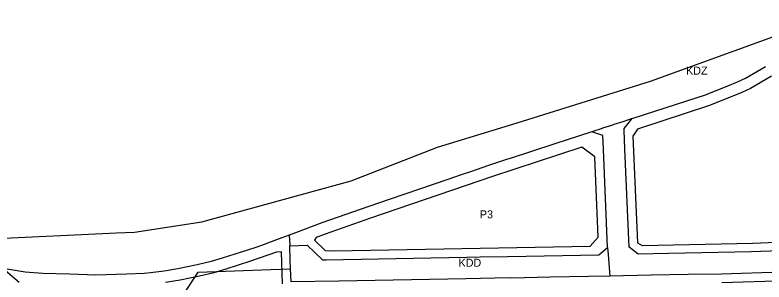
# Model space of a CAD drawing. Extents: x 7428080 to 7432143, y 5545880 to 5549217.
# Drawn here: x 7428821 to 7429340, y 5547123 to 5547308 of the extents above; entities that cross this region are included whole.
import ezdxf

# ---------------------------------------------------------------- set-up
doc = ezdxf.new("R2010")
doc.units = 0
for name, color, linetype in [('CZ_L_linie rozgraniczające tereny o różnym przeznaczeniu oraz różnych warunkach ich zabudowy i zagospodarowania', 7, 'Continuous'), ('CZ_L_maksymalne nieprzekraczalne linie zabudowy', 7, 'Continuous'), ('CZ_L_opisy_linie rozgraniczające tereny o różnym przeznaczeniu oraz różnych warunkach ich zabudowy i zagospodarowania', 7, 'Continuous'), ('info', 7, 'Continuous')]:
    doc.layers.add(name, color=color, linetype=linetype)

msp = doc.modelspace()

# ---------------------------------------------------------------- linework, layer by layer
at = {"layer": 'CZ_L_linie rozgraniczające tereny o różnym przeznaczeniu oraz różnych warunkach ich zabudowy i zagospodarowania'}
for p, q in [((7429327.56, 5547264.7), (7429341.29, 5547272.65)), ((7429321.92, 5547262.06), (7429327.56, 5547264.7)), ((7429299.72, 5547253.05), (7429315.35, 5547259.36)), ((7429315.35, 5547259.36), (7429321.92, 5547262.06)), ((7429272.6, 5547244.17), (7429299.72, 5547253.05)), ((7429248.99, 5547236.51), (7429272.6, 5547244.17)), ((7429235.22, 5547232.03), (7429228.35, 5547229.8)), ((7429236.15, 5547232.33), (7429235.22, 5547232.03)), ((7429242.37, 5547234.36), (7429236.15, 5547232.33)), ((7429243.13, 5547234.6), (7429242.37, 5547234.36)), ((7429243.25, 5547234.64), (7429243.13, 5547234.6)), ((7429248.99, 5547236.51), (7429243.25, 5547234.64)), ((7429243.34, 5547229.61), (7429248.99, 5547236.51)), ((7429220.98, 5547227.4), (7429194.56, 5547218.81)), ((7429228.18, 5547229.74), (7429220.98, 5547227.4)), ((7429228.55, 5547224.8), (7429220.98, 5547227.4)), ((7429228.35, 5547229.8), (7429228.18, 5547229.74)), ((7429243.38, 5547228.52), (7429243.34, 5547229.61)), ((7429243.93, 5547215.27), (7429243.38, 5547228.52)), ((7429228.95, 5547215.29), (7429228.55, 5547224.8)), ((7429194.56, 5547218.81), (7429164.27, 5547208.88)), ((7429231.75, 5547147.15), (7429228.95, 5547215.29)), ((7429246.74, 5547147.43), (7429243.93, 5547215.27)), ((7429158.43, 5547206.95), (7429148.58, 5547203.66)), ((7429161.8, 5547208.07), (7429158.43, 5547206.95)), ((7429164.27, 5547208.88), (7429161.8, 5547208.07)), ((7429148.58, 5547203.66), (7429137.61, 5547199.91)), ((7429130.34, 5547197.42), (7429121.21, 5547194.29)), ((7429137.61, 5547199.91), (7429130.34, 5547197.42)), ((7429121.21, 5547194.29), (7429081.1, 5547180.55)), ((7429081.1, 5547180.55), (7429066.41, 5547175.5)), ((7429066.41, 5547175.5), (7429033.84, 5547164.13)), ((7429033.84, 5547164.13), (7429015.51, 5547157.29)), ((7429011.21, 5547155.68), (7429005.98, 5547153.73)), ((7429015.51, 5547157.29), (7429011.21, 5547155.68)), ((7429011.21, 5547155.68), (7429011.46, 5547148.89)), ((7428998.58, 5547150.97), (7428991.91, 5547148.54)), ((7429005.98, 5547153.73), (7428998.58, 5547150.97)), ((7429011.46, 5547148.89), (7429011.49, 5547148.19)), ((7429011.49, 5547148.19), (7429023.48, 5547148.64)), ((7429023.48, 5547148.64), (7429034.29, 5547138.6)), ((7428982.2, 5547145.26), (7428964.74, 5547139.68)), ((7428987.98, 5547147.1), (7428982.2, 5547145.26)), ((7428991.91, 5547148.54), (7428987.98, 5547147.1)), ((7429011.86, 5547138.2), (7429011.49, 5547148.19)), ((7429225.71, 5547142.04), (7429231.75, 5547147.15)), ((7429231.75, 5547147.15), (7429232.19, 5547142.16)), ((7429252.97, 5547142.55), (7429246.74, 5547147.43)), ((7429331.73, 5547144.02), (7429274.15, 5547142.94)), ((7429351.35, 5547144.79), (7429331.73, 5547144.02)), ((7428964.74, 5547139.68), (7428956.98, 5547137.37)), ((7429034.29, 5547138.6), (7429036.78, 5547138.65)), ((7429036.78, 5547138.65), (7429109.22, 5547139.96)), ((7429109.22, 5547139.96), (7429134.17, 5547140.41)), ((7429134.17, 5547140.41), (7429143.54, 5547140.58)), ((7429143.54, 5547140.58), (7429162.55, 5547140.92)), ((7429162.55, 5547140.92), (7429162.61, 5547140.86)), ((7429162.61, 5547140.86), (7429225.71, 5547142.04)), ((7429232.19, 5547142.16), (7429233.5, 5547127.25)), ((7429274.15, 5547142.94), (7429252.97, 5547142.55)), ((7428947.3, 5547135.11), (7428933.97, 5547132.32)), ((7428956.98, 5547137.37), (7428947.3, 5547135.11)), ((7429012.08, 5547132.28), (7429011.86, 5547138.2)), ((7428812.73, 5547132.54), (7428823.86, 5547123.08)), ((7428827.96, 5547129.92), (7428814.29, 5547132.24)), ((7428840.36, 5547129.06), (7428827.96, 5547129.92)), ((7428858.99, 5547128.56), (7428840.36, 5547129.06)), ((7428876.94, 5547127.88), (7428858.99, 5547128.56)), ((7428898.35, 5547128.54), (7428876.94, 5547127.88)), ((7428910.64, 5547129.14), (7428898.35, 5547128.54)), ((7428914.87, 5547129.61), (7428910.64, 5547129.14)), ((7428924.48, 5547130.66), (7428914.87, 5547129.61)), ((7428933.97, 5547132.32), (7428924.48, 5547130.66)), ((7428938.04, 5547114.8), (7428948.07, 5547129.89)), ((7428948.07, 5547129.89), (7428998.31, 5547131.77)), ((7428998.31, 5547131.77), (7429012.08, 5547132.28)), ((7429012.42, 5547123.2), (7429012.08, 5547132.28)), ((7429287.85, 5547128.33), (7429262.1, 5547127.82)), ((7429310.91, 5547128.6), (7429287.85, 5547128.33)), ((7429355.44, 5547129.96), (7429310.91, 5547128.6)), ((7429045.45, 5547123.8), (7429012.42, 5547123.2)), ((7429133.5, 5547125.4), (7429045.45, 5547123.8)), ((7429163.75, 5547125.95), (7429133.5, 5547125.4)), ((7429165.19, 5547125.91), (7429163.75, 5547125.95)), ((7429192.1, 5547126.43), (7429165.19, 5547125.91)), ((7429218.6, 5547126.95), (7429192.1, 5547126.43)), ((7429233.5, 5547127.25), (7429218.6, 5547126.95)), ((7429262.1, 5547127.82), (7429233.5, 5547127.25))]:
    msp.add_line(p, q, dxfattribs=at)
at = {"layer": 'CZ_L_maksymalne nieprzekraczalne linie zabudowy'}
for points in [[(7429345.53, 5547265.87), (7429330.95, 5547257.45), (7429324.96, 5547254.66), (7429302.58, 5547245.58), (7429252.6, 5547229.27), (7429249.45, 5547224.3), (7429252.62, 5547150.44), (7429255.88, 5547148.43)], [(7429219.68, 5547147.93), (7429225.38, 5547154.29), (7429223.03, 5547210.12), (7429214.12, 5547216.76), (7429152.02, 5547196.38), (7429067.43, 5547167.38), (7429036.17, 5547156.46), (7429029.81, 5547154.09), (7429028.7, 5547152.14), (7429036.04, 5547145.09), (7429042.18, 5547144.77), (7429219.68, 5547147.93)], [(7429255.65, 5547148.6), (7429332.53, 5547150.06), (7429370.96, 5547151.68)], [(7429006.54, 5547121.84), (7429005.69, 5547144.03), (7429002.22, 5547143.88), (7428984.38, 5547137.56), (7428967.14, 5547132.05), (7428958.88, 5547129.6), (7428948.95, 5547127.28), (7428935.6, 5547124.49), (7428925.35, 5547122.71)], [(7429355.68, 5547123.96), (7429311.09, 5547122.6)]]:
    msp.add_lwpolyline(points, dxfattribs=at)
at = {"layer": 'info'}
for p, q in [((7429113.92, 5547216.77), (7429169.2, 5547233.58)), ((7429054.16, 5547193.29), (7429113.92, 5547216.77)), ((7428891.33, 5547157.25), (7428903.88, 5547157.76))]:
    msp.add_line(p, q, dxfattribs=at)
for points in [[(7429169.2, 5547233.58), (7429261.57, 5547262.53), (7429356.72, 5547297.08), (7429356.72, 5547302.84), (7429356.86, 5547308.44)], [(7428903.88, 5547157.76), (7428950.54, 5547164.84), (7429054.16, 5547193.29)], [(7428683.22, 5547152.69), (7428716.69, 5547157), (7428739.47, 5547157.94), (7428759.33, 5547156.24), (7428767.35, 5547152.83), (7428770.62, 5547151.44), (7428790.34, 5547152.39), (7428803.45, 5547153.02), (7428891.33, 5547157.25)]]:
    msp.add_lwpolyline(points, dxfattribs=at)

# ---------------------------------------------------------------- texts
at = {"layer": 'CZ_L_opisy_linie rozgraniczające tereny o różnym przeznaczeniu oraz różnych warunkach ich zabudowy i zagospodarowania'}
for s, p in [('KDZ', (7429286.32, 5547267.06)), ('P3', (7429143.34, 5547167.34)), ('KDD', (7429128.58, 5547133.73))]:
    msp.add_text(s, height=5.549, dxfattribs=at).set_placement(p)

doc.saveas('drawing.dxf')
